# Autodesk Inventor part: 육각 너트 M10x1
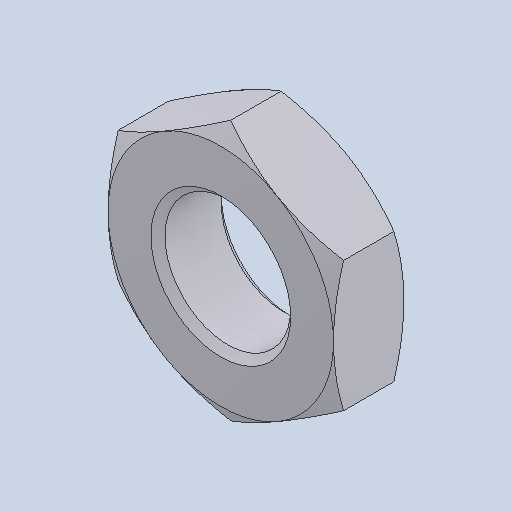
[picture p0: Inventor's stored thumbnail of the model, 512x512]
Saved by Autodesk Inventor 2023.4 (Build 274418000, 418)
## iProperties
Created: 2024-04
Part Number: 육각 너트 M10x1
Material: 강철, 연강
Description: 6각 가는 너트 - 이중 모따기(부품 등급 A) - 정밀 나사산
Document SubType Name: Modeling
Designer: EDU
Density: 7.85 g/cm^3
Appearance: 기본값
Author: jhkim
Sending System: Autodesk Inventor 2025
Preprocessor: ST-DEVELOPER v20
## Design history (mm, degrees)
node "육각 너트 M10x11"
node "솔리드1"
body "Solid1"
